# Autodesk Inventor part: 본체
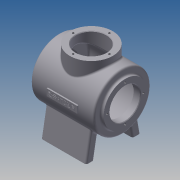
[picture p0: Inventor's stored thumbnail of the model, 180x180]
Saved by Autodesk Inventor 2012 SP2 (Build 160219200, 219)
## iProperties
Created: 2015-01
Part Number: 본체
Material: 알루미늄-6061
Document SubType Name: Modeling
Designer: cad-02
Mass: 1024.69 g
Surface Area: 1060.49 cm^2
Volume: 378.115 cm^3
Density: 2.71 g/cm^3
Author: cad-02
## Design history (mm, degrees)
sketch "스케치1"
  geometry: C1 r 50 at (0, 0); 1 further point
  constraints: 1 centre point, 1 coincident
  dimensions: "d0" = 100 diameter of C1
extrude "돌출1" new body sketch "스케치1" distance "d1" = 112; taper "d2" = 0 deg
sketch "스케치2"
  geometry: C1 r 50 at (0, 0) reference; C2 r 38 at (0, 0)
  constraints: 1 centre point, 1 coincident
  dimensions: "d3" = 76 diameter of C2
extrude "돌출2" join sketch "스케치2" distance "d4" = 5; taper "d5" = 0 deg
sketch "스케치3"
  geometry: C1 r 50 at (0, 0) reference; C2 r 38 at (0, 0)
  constraints: 1 centre point, 1 coincident
  dimensions: "d6" = 76 diameter of C2
extrude "돌출3" join sketch "스케치3" distance "d7" = 5; taper "d8" = 0 deg
node "작업 평면1"
sketch "스케치4"
  geometry: L1 (0, 50)-(112, 50) reference; L2 (0, 50)-(0, -50) reference; L3 (-5, -38)-(-5, 38) reference; C1 r 38 at (57, 0); 2 further points
  constraints: 1 centre point, 1 horizontal alignment, 1 midpoint
  dimensions: "d10" = 76 diameter of C1; "d107" = 62 distance from line of C1.centre L3
extrude "돌출4" join sketch "스케치4" stored distance "d11" = 5; taper "d12" = 0 deg
hole "구멍1" diameter "d15" = 54; stored, may be unused: countersink angle "d19" = 90 deg, drill point angle "d21" = 0 deg; dims "d13" = 10, "d14" = 10, "d16" = 6, "d17" = 4, "d18" = 2, "d20" = 40
hole "구멍2" diameter "d24" = 54; stored, may be unused: countersink angle "d28" = 90 deg, drill point angle "d30" = 0 deg; dims "d22" = 10, "d23" = 10, "d25" = 6, "d26" = 4, "d27" = 2, "d29" = 12
hole "구멍3" diameter "d33" = 90; stored, may be unused: countersink angle "d37" = 90 deg, drill point angle "d39" = 0 deg; dims "d31" = 10, "d32" = 10, "d34" = 6, "d35" = 4, "d36" = 2, "d38" = 97
hole "구멍4" diameter "d42" = 54; stored, may be unused: countersink angle "d46" = 90 deg, drill point angle "d48" = 0 deg; dims "d43" = 6, "d44" = 4, "d45" = 2, "d47" = 13, "d49" = 10, "d50" = 10
node "작업 평면3"
sketch "스케치8"
  geometry: L1 (30.865, -39.336)-(80, -48); L2 (80, -48)-(80, -34); L3 (80, -34)-(41.901, -27.282); L4 (80, 34)-(80, 48); L5 (80, 48)-(30.865, 39.336); L6 (41.901, 27.282)-(80, 34); C1 r 45 at (0, 0) reference; A1 r 50 centre (0, 0) between (30.865, -39.336) and (41.901, -27.282) reference; 1 further point
  constraints: 12 end point, 4 point on circle, 2 equal length, 1 collinear, 1 parallel, 1 vertical
  dimensions: "d51" = 96 distance of L4.end L1.end; "d52" = 80 deg angle of L6 L4; "d53" = 100 deg angle of L4 L5; "d54" = 100 deg angle of L2 L1; "d55" = 80 distance from line of point (0, 0) L2; "d108" = 14 distance of L2.end L1.end
extrude "돌출5" join sketch "스케치8" stored distance "d57" = 80; taper "d58" = 0 deg
sketch "스케치10"
  geometry: C1 r 27 at (0, 0) reference; 1 further point
  constraints: 1 horizontal alignment
  dimensions: "d59" = 32 distance of C1.centre point (-32, 0)
hole "구멍5" sketch "스케치10" at (-32, 0) diameter "d60" = 3.242; stored, may be unused: countersink angle "d64" = 90 deg, drill point angle "d66" = 118 deg; dims "d61" = 8, "d62" = 4, "d63" = 2, "d65" = 10
sketch "스케치11"
  geometry: C1 r 27 at (0, 0) reference; 1 further point
  constraints: 1 horizontal alignment
  dimensions: "d70" = 32 distance of point (32, 0) C1.centre
hole "구멍6" sketch "스케치11" at (32, 0) diameter "d71" = 3.242; stored, may be unused: countersink angle "d75" = 90 deg, drill point angle "d77" = 118 deg; dims "d72" = 8, "d73" = 4, "d74" = 2, "d76" = 10
sketch "스케치12"
  geometry: C1 r 27 at (0, 0) reference; 2 further points
  constraints: 1 horizontal alignment
  dimensions: "d81" = 32 distance of C1.centre point (32, 0)
hole "구멍7" sketch "스케치12" at (32, 0) diameter "d82" = 3.242; stored, may be unused: countersink angle "d86" = 90 deg, drill point angle "d88" = 118 deg; dims "d83" = 8, "d84" = 4, "d85" = 2, "d87" = 10
node "작업 평면4"
sketch "스케치15"
  geometry: L1 (30, 6)-(30, -6); L2 (30, -6)-(84, -6); L3 (84, -6)-(84, 6); L4 (84, 6)-(30, 6); L5 (-5, -38)-(-5, 38) reference; L6 (57, 6)-(57, -6); 2 further points
  constraints: 10 end point, 3 midpoint, 2 parallel, 1 horizontal alignment, 1 perpendicular, 1 vertical
  dimensions: "d93" = 12 distance between parallel lines of L4 L2; "d94" = 54 distance between parallel lines of L3 L1; "d95" = 62 distance between parallel lines of L6 L5
extrude "돌출6" join sketch "스케치15" stored distance "d96" = 80; taper "d97" = 0 deg
sketch "스케치16"
  geometry: L1 (30, 6)-(30, -6) reference; L2 (84, 6)-(30, 6) reference; 4 further points
  constraints: 2 midpoint, 1 horizontal alignment, 1 vertical alignment, 1 other
feature "엠보싱1" sketch "스케치16" dims "d1" = 112, "d10" = 76, "d98" = 0.5, "d99" = 0, "d107" = 62
fillet "모깎기1" dims "d100" = 3
fillet "모깎기2" dims "d101" = 3
fillet "모깎기3" dims "d102" = 3
chamfer "모따기1" distance "d103" = 1; stored, may be unused: second distance "d104" = 2, angle "d105" = 45 deg
fillet "모깎기4" dims "d106" = 3
sketch "스케치21"
  geometry: 1 further point
node "솔리드1"
pattern_circular "원형 패턴1" dims angle "d68" = 360 deg
pattern_circular "원형 패턴2" dims angle "d79" = 360 deg
pattern_circular "원형 패턴3" dims angle "d90" = 360 deg
other parameters: "d9" = 62, "d92" = -52
